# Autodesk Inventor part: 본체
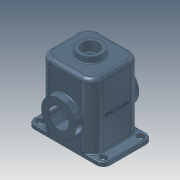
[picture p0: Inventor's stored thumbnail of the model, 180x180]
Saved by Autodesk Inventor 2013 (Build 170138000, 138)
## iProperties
Company: 한국ATC센터
Created: 2014-10
Part Number: 본체
Document SubType Name: Modeling
Designer: 한국ATC센터
Density: 1 g/cm^3
Material: 일반
Mass: 1088.52 g
Surface Area: 2150.09 cm^2
Volume: 1088.52 cm^3
Author: KYOUNG IL JANG
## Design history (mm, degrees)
sketch "스케치1"
  geometry: L1 (-70, 65)-(70, 65); L2 (70, 65)-(70, -65); L3 (70, -65)-(-70, -65); L4 (-70, -65)-(-70, 65); 3 further points
  constraints: 8 end point, 2 midpoint, 2 parallel, 1 horizontal, 1 horizontal alignment, 1 perpendicular, 1 vertical alignment
  dimensions: "d0" = 140 distance of L2.end L3.end; "d68" = 130 distance of L3.end L1.start
extrude "돌출1" new body sketch "스케치1" distance "d1" = 180; taper "d2" = 0 deg
fillet "모깎기1" dims "d3" = 20
feature "쉘1" dims "d4" = 10
sketch "스케치2"
  geometry: L1 (-70, 45)-(-70, -45) reference; L2 (-50, -65)-(-82, -65); L3 (-82, 65)-(-50, 65); L4 (-85, 57)-(-82, 57); L5 (-82, 41)-(-85, 41); L6 (-100, 47)-(-100, -47); A1 r 20 centre (-50, 45) between (-50, 65) and (-70, 45) reference; A2 r 20 centre (-50, -45) between (-70, -45) and (-50, -65) reference; A3 r 8 centre (-82, 49) between (-82, 41) and (-82, 57); A4 r 8 centre (-85, 49) between (-85, 57) and (-85, 41); A5 r 18 centre (-82, 47) between (-82, 65) and (-100, 47); A6 r 18 centre (-82, -47) between (-100, -47) and (-82, -65); 1 further point
  constraints: 10 end point, 9 tangent, 8 point on circle, 4 centre point, 2 parallel, 2 perpendicular, 1 equal radius
  dimensions: "d6" = 49 vertical distance of point (0, 0) A3.centre; "d8" = 16 distance between parallel lines of L4 L5; "d64" = 18 radius of A5; "d65" = 12 distance from line of A3.centre L1; "d66" = 30 distance between parallel lines of L6 L1; "d67" = 3 distance of A4.centre A3.centre
extrude "돌출2" join sketch "스케치2" distance "d9" = 10; taper "d10" = 0 deg
extrude "돌출3" cut sketch "스케치2" stored distance "d11" = 10; taper "d12" = 0 deg
sketch "스케치3"
  geometry: L1 (-65, 0)-(-65, 180) reference; L2 (-55, 0)-(-55, 170) reference; L3 (-83, 75)-(-51, 75); L4 (45, 0)-(-45, 0) reference; L5 (-83, 75)-(-83, 120.5); L6 (-83, 120.5)-(-55, 120.5); L7 (-55, 120.5)-(-51, 116.5); L8 (-51, 116.5)-(-51, 75); 2 further points
  constraints: 10 end point, 4 perpendicular, 1 point on line
  dimensions: "d13" = 75 distance between parallel lines of L3 L4; "d14" = 18 distance from line of L1 L3.start; "d15" = 4 distance from line of L3.end L2; "d16" = 91 diameter of L6 L3; "d17" = 135 deg angle of L7 L2
revolve "회전1" sketch "스케치3" stored, may be unused: angle "d18" = 90 deg
sketch "스케치4"
  geometry: C1 r 45.5 at (0, 0) reference; 2 further points
  constraints: 1 vertical alignment
  dimensions: "d19" = 35 distance of C1.centre point (0, 35)
hole "구멍1" sketch "스케치4" at (0, 35) diameter "d20" = 3.459; stored, may be unused: countersink angle "d24" = 90 deg, drill point angle "d26" = 118 deg; dims "d21" = 13, "d22" = 4, "d23" = 2, "d25" = 16
fillet "모깎기2" dims "d30" = 3
hole "구멍2" diameter "d33" = 52; stored, may be unused: countersink angle "d37" = 90 deg, drill point angle "d39" = 118 deg; dims "d31" = 10, "d32" = 10, "d34" = 13, "d35" = 4, "d36" = 2, "d38" = 16
sketch "스케치5"
  geometry: C1 r 31 at (0, 0); 1 further point
  constraints: 1 centre point, 1 coincident
  dimensions: "d40" = 62 diameter of C1
extrude "돌출4" join sketch "스케치5" distance "d41" = 15; taper "d42" = 0 deg
hole "구멍3" diameter "d45" = 43; stored, may be unused: countersink angle "d49" = 90 deg, drill point angle "d51" = 118 deg; dims "d43" = 10, "d44" = 10, "d46" = 13, "d47" = 4, "d48" = 2, "d50" = 16
fillet "모깎기3" dims "d52" = 3
fillet "모깎기4" dims "d53" = 3
chamfer "모따기1" distance "d55" = 1; stored, may be unused: second distance "d56" = 2, angle "d57" = 45 deg
sketch "스케치6"
  geometry: 2 further points
  constraints: 1 vertical alignment, 1 other
  dimensions: "d71" = 90 distance of point (0, 0) point (0, 90)
feature "엠보싱2" sketch "스케치6" dims "d0" = 140, "d68" = 130, "d72" = 1, "d73" = 0
fillet "모깎기6" dims "d74" = 10
sketch "스케치7"
  geometry: C1 r 15 at (0, 0); C2 r 21.5 at (0, 0) reference; C3 r 25 at (0, 0); 1 further point
  constraints: 2 centre point, 2 coincident
  dimensions: "d61" = 30 diameter of C1; "d75" = 50 diameter of C3
extrude "돌출5" join sketch "스케치7" distance "d62" = 10; taper "d63" = 0 deg
feature "면 이동1" dims "d76" = 1
fillet "모깎기7" dims "d77" = 3
node "솔리드1"
mirror "대칭1"
mirror "대칭2"
pattern_circular "원형 패턴1" dims angle "d28" = 360 deg
mirror "대칭3"
